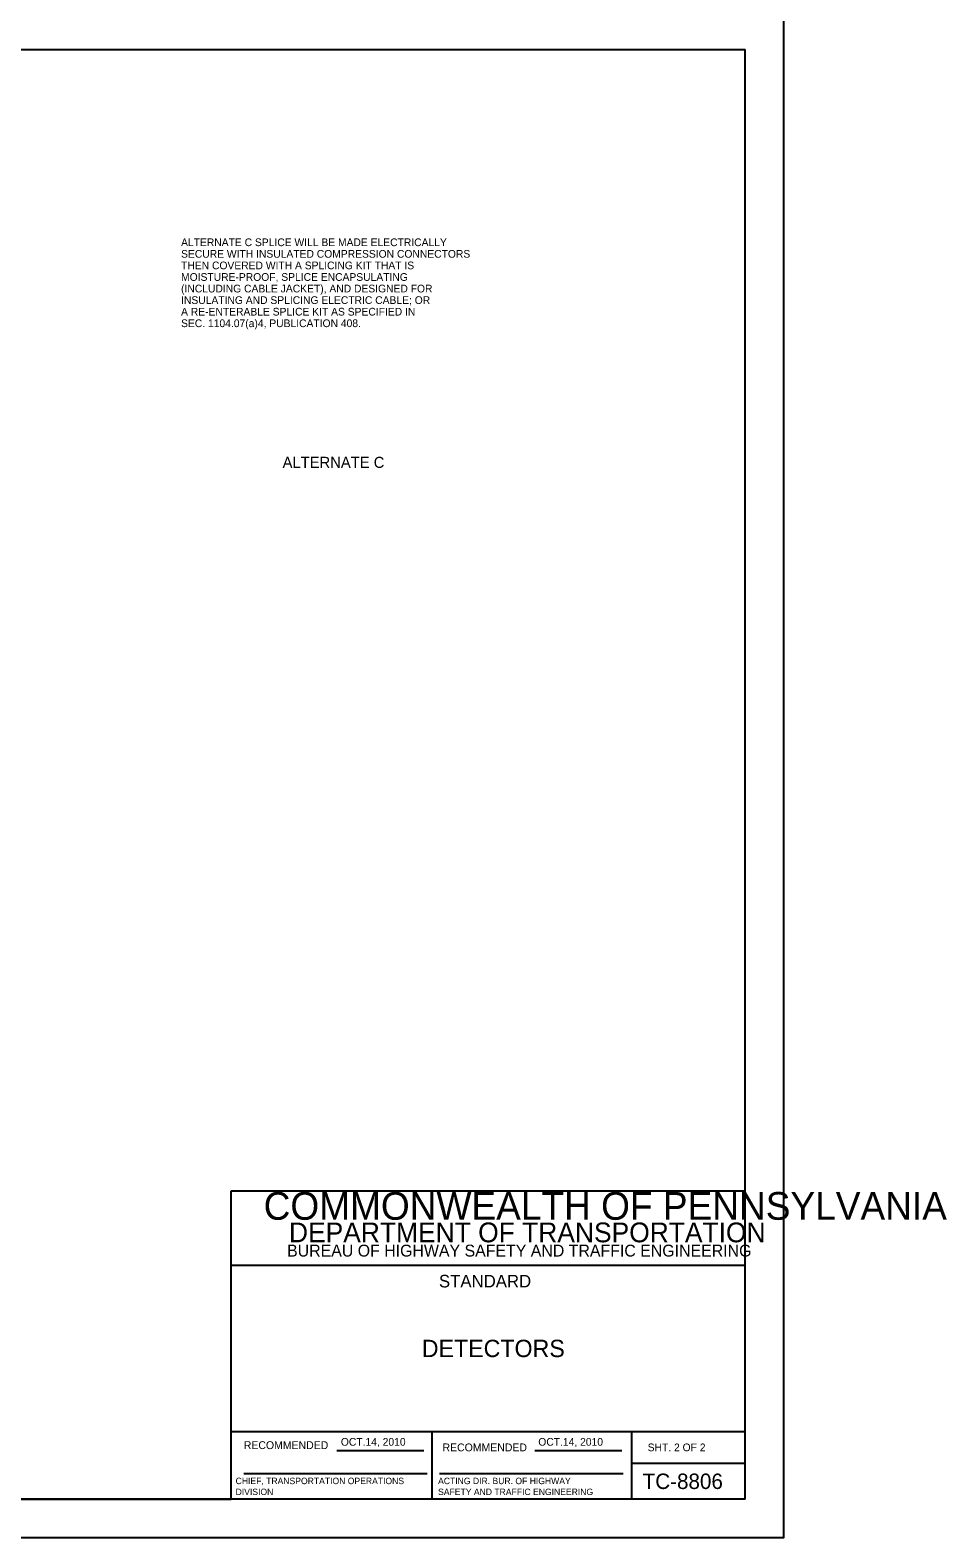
# Model space of a CAD drawing. Extents: x 2709 to 3899, y 22 to 1210.
# Drawn here: x 3257 to 3613, y 22 to 609 of the extents above; entities that cross this region are included whole.
import ezdxf

# ---------------------------------------------------------------- set-up
doc = ezdxf.new("R2010")
doc.units = 0
for name, color, linetype in [('1', 7, 'Continuous'), ('2', 7, 'Continuous'), ('4', 7, 'Continuous'), ('Default', 7, 'Continuous'), ('PLT-BNDY', 7, 'Continuous')]:
    doc.layers.add(name, color=color, linetype=linetype)

msp = doc.modelspace()

# ---------------------------------------------------------------- linework, layer by layer
at = {"layer": '1'}
for p, q in [((2748.86, 601.17), (3534.86, 601.17)), ((3534.86, 37.17), (3534.86, 601.17)), ((3334.86, 37.17), (3334.86, 157.17)), ((3334.86, 157.17), (3534.86, 157.17)), ((3534.86, 128.17), (3334.86, 128.17)), ((3334.86, 63.55), (3534.86, 63.55)), ((3412.86, 63.55), (3412.86, 37.17)), ((3490.73, 37.17), (3490.73, 63.55)), ((3375.9, 56.2), (3409.82, 56.2)), ((3452.99, 56.2), (3486.91, 56.2)), ((3339.74, 47.21), (3411.07, 47.21)), ((3415.95, 47.21), (3487.41, 47.21)), ((3490.73, 51.17), (3534.86, 51.17)), ((3534.86, 37.17), (2748.86, 37.17)), ((2748.86, 37.17), (3334.86, 37.17))]:
    msp.add_line(p, q, dxfattribs=at)
at = {"layer": 'PLT-BNDY'}
msp.add_lwpolyline([(2708.86, 616.17), (3549.86, 616.17), (3549.86, 22.17), (2708.86, 22.17)], close=True, dxfattribs=at)

# ---------------------------------------------------------------- texts
at = {"layer": '1'}
for s, height, p in [('COMMONWEALTH OF PENNSYLVANIA', 10.7828, (3347.45, 145.9)), ('DEPARTMENT OF TRANSPORTATION', 7.6837, (3357.31, 137.15)), ('BUREAU OF HIGHWAY SAFETY AND TRAFFIC ENGINEERING', 4.6253, (3356.58, 131.59)), ('DETECTORS', 6.75, (3409.01, 92.48)), ('RECOMMENDED', 3.0516, (3339.73, 56.7)), ('OCT.14, 2010', 3, (3377.51, 58.01)), ('RECOMMENDED', 3.0516, (3417.08, 55.82)), ('SHT. 2 OF 2', 3, (3496.94, 55.86)), ('TC-8806', 6, (3495, 41.17))]:
    msp.add_text(s, height=height, dxfattribs=at).set_placement(p)
msp.add_text('OCT.14, 2010', height=3, rotation=360, dxfattribs=at).set_placement((3454.36, 58.01))
at = {"layer": '2'}
for s, height, p in [('ALTERNATE C SPLICE WILL BE MADE ELECTRICALLY', 3, (3315.31, 524.65)), ('SECURE WITH INSULATED COMPRESSION CONNECTORS', 3, (3315.31, 520.15)), ('THEN COVERED WITH A SPLICING KIT THAT IS', 3, (3315.31, 515.65)), ('MOISTURE-PROOF, SPLICE ENCAPSULATING', 3, (3315.31, 511.15)), ('(INCLUDING CABLE JACKET), AND DESIGNED FOR', 3, (3315.31, 506.65)), ('INSULATING AND SPLICING ELECTRIC CABLE; OR', 3, (3315.31, 502.15)), ('A RE-ENTERABLE SPLICE KIT AS SPECIFIED IN', 3, (3315.31, 497.65)), ('SEC. 1104.07(a)4, PUBLICATION 408.', 3, (3315.31, 493.15)), ('ALTERNATE C', 4.3, (3354.83, 438.39))]:
    msp.add_text(s, height=height, dxfattribs=at).set_placement(p)
at = {"layer": '4'}
msp.add_text('STANDARD', height=4.881, rotation=360, dxfattribs=at).set_placement((3415.69, 119.59))
at = {"layer": 'Default'}
for s, p in [('CHIEF, TRANSPORTATION OPERATIONS', (3336.54, 43.06)), ('DIVISION', (3336.54, 38.81)), ('ACTING DIR. BUR. OF HIGHWAY', (3415.35, 43.06)), ('SAFETY AND TRAFFIC ENGINEERING', (3415.35, 38.81))]:
    msp.add_text(s, height=2.5, dxfattribs=at).set_placement(p)

doc.saveas('drawing.dxf')
